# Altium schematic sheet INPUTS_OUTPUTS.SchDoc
size A; SheetNumber: 5; SheetTotal: 5
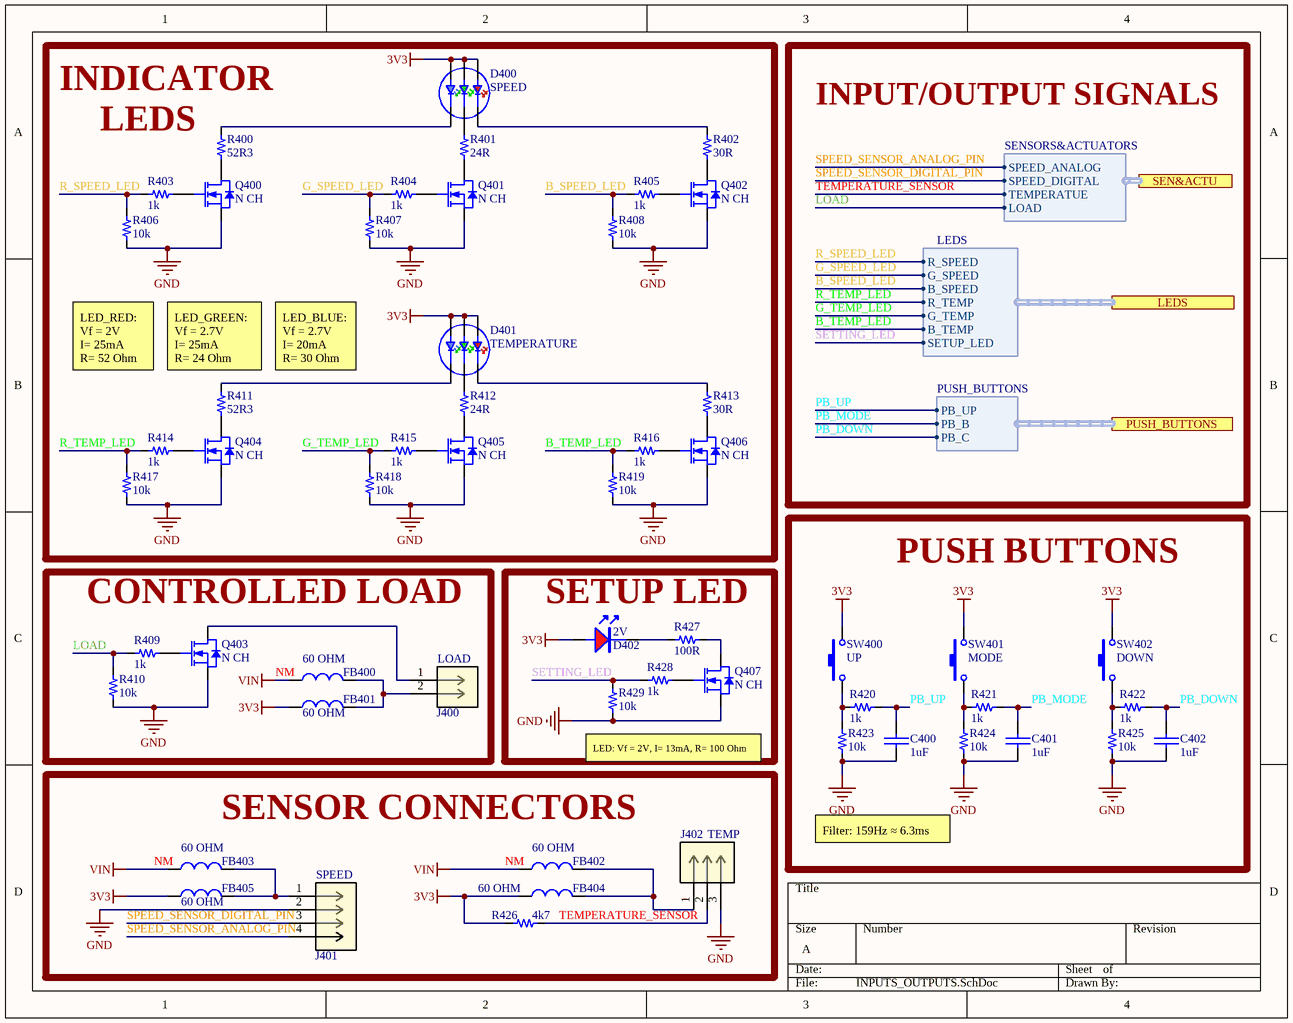
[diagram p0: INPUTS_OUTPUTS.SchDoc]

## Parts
C400  value 1uF  [0603_cap]  (hidden comment: 1uF 50V)
C401  value 1uF  [0603_cap]  (hidden comment: 1uF 50V)
C402  value 1uF  [0603_cap]  (hidden comment: 1uF 50V)
D400  SPEED  [RGB_NS_3.5X3.7]
D401  TEMPERATURE  [RGB_NS_3.5X3.7]
D402  2V  [0805_LED]
FB400  value 60 OHM  Usage: NM  [0603_fb]  (hidden comment: 60OHM 2A)
FB401  value 60 OHM  [0603_fb]  (hidden comment: 60OHM 2A)
FB402  value 60 OHM  Usage: NM  [0603_fb]  (hidden comment: 60OHM 2A)
FB403  value 60 OHM  Usage: NM  [0603_fb]  (hidden comment: 60OHM 2A)
FB404  value 60 OHM  [0603_fb]  (hidden comment: 60OHM 2A)
FB405  value 60 OHM  [0603_fb]  (hidden comment: 60OHM 2A)
J400  LOAD  [CON_2X1_TH_2.54MM]
J401  SPEED  [CON_4X1_TH_2.54MM]
J402  TEMP  [CON_3X1_TH_2.54MM]
Q400  N CH  [SOT_23_3]
Q401  N CH  [SOT_23_3]
Q402  N CH  [SOT_23_3]
Q403  N CH  [SOT_23_3]
Q404  N CH  [SOT_23_3]
Q405  N CH  [SOT_23_3]
Q406  N CH  [SOT_23_3]
Q407  N CH  [SOT_23_3]
R400  value 52R3  [0603_res]  (hidden comment: 52R3 1/10W)
R401  value 24R  [0603_res]  (hidden comment: 24R 1/10W)
R402  value 30R  [0603_res]  (hidden comment: 30 1/10W)
R403  value 1k  [0603_res]  (hidden comment: 1k 1/10W)
R404  value 1k  [0603_res]  (hidden comment: 1k 1/10W)
R405  value 1k  [0603_res]  (hidden comment: 1k 1/10W)
R406  value 10k  [0603_res]  (hidden comment: 10k 1/10W)
R407  value 10k  [0603_res]  (hidden comment: 10k 1/10W)
R408  value 10k  [0603_res]  (hidden comment: 10k 1/10W)
R409  value 1k  [0603_res]  (hidden comment: 1k 1/10W)
R410  value 10k  [0603_res]  (hidden comment: 10k 1/10W)
R411  value 52R3  [0603_res]  (hidden comment: 52R3 1/10W)
R412  value 24R  [0603_res]  (hidden comment: 24R 1/10W)
R413  value 30R  [0603_res]  (hidden comment: 30 1/10W)
R414  value 1k  [0603_res]  (hidden comment: 1k 1/10W)
R415  value 1k  [0603_res]  (hidden comment: 1k 1/10W)
R416  value 1k  [0603_res]  (hidden comment: 1k 1/10W)
R417  value 10k  [0603_res]  (hidden comment: 10k 1/10W)
R418  value 10k  [0603_res]  (hidden comment: 10k 1/10W)
R419  value 10k  [0603_res]  (hidden comment: 10k 1/10W)
R420  value 1k  [0603_res]  (hidden comment: 1k 1/10W)
R421  value 1k  [0603_res]  (hidden comment: 1k 1/10W)
R422  value 1k  [0603_res]  (hidden comment: 1k 1/10W)
R423  value 10k  [0603_res]  (hidden comment: 10k 1/10W)
R424  value 10k  [0603_res]  (hidden comment: 10k 1/10W)
R425  value 10k  [0603_res]  (hidden comment: 10k 1/10W)
R426  value 4k7  [0603_res]  (hidden comment: 4k7 1/10W)
R427  value 100R  [0603_res]  (hidden comment: 100R 1/10W)
R428  value 1k  [0603_res]  (hidden comment: 1k 1/10W)
R429  value 10k  [0603_res]  (hidden comment: 10k 1/10W)
SW400  UP  [Sw_PUSH_4.5x4.5x5mm]
SW401  MODE  [Sw_PUSH_4.5x4.5x5mm]
SW402  DOWN  [Sw_PUSH_4.5x4.5x5mm]

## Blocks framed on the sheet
PUSH BUTTONS: C400-C402 R420-R425 SW400-SW402
CONTROLLED LOAD: FB400 FB401 J400 Q403 R409 R410
SETUP LED: D402 Q407 R427-R429
SENSOR CONNECTORS: FB402-FB405 J401 J402 R426

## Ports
LEDS (harness LEDS, see main[3C], MCU[4C]), PUSH_BUTTONS (harness PUSH_BUTTONS, see main[3C], MCU[4C]), SEN&ACTU (harness SENSORS&ACTUATORS, see main[3C], MCU[4C])

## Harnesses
LEDS: R_SPEED, G_SPEED, B_SPEED, R_TEMP, G_TEMP, B_TEMP, SETUP_LED
SENSORS&ACTUATORS: SPEED_ANALOG, SPEED_DIGITAL, TEMPERATUE, LOAD
PUSH_BUTTONS: PB_UP, PB_B, PB_C

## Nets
3V3: D400.4 D400.5 D400.6 D401.4 D401.5 D401.6 D402.1(A) FB401.1 FB404.1 FB405.1 R426.1 SW400.2 SW401.2 SW402.2
GND: C400.1 C401.1 C402.1 J401.2 J402.3 Q400.2(S) Q401.2(S) Q402.2(S) Q403.2(S) Q404.2(S) Q405.2(S) Q406.2(S) Q407.2(S) R406.1 R407.1 R408.1 R410.1 R417.1 R418.1 R419.1 R423.1 R424.1 R425.1 R429.1
VIN: FB400.1 FB402.1 FB403.1
B_SPEED_LED: R405.1 R408.2 ; port LEDS.B_SPEED
B_TEMP_LED: R416.1 R419.2 ; port LEDS.B_TEMP
G_SPEED_LED: R404.1 R407.2 ; port LEDS.G_SPEED
G_TEMP_LED: R415.1 R418.2 ; port LEDS.G_TEMP
LOAD: R409.1 R410.2 ; port SEN&ACTU.LOAD
PB_DOWN: C402.2 R422.2 ; port PUSH_BUTTONS.PB_C
PB_MODE: C401.2 R421.2 ; port PUSH_BUTTONS.PB_B
PB_UP: C400.2 R420.2 ; port PUSH_BUTTONS.PB_UP
R_SPEED_LED: R403.1 R406.2 ; port LEDS.R_SPEED
R_TEMP_LED: R414.1 R417.2 ; port LEDS.R_TEMP
SETTING_LED: R428.1 R429.2 ; port LEDS.SETUP_LED
SPEED_SENSOR_ANALOG_PIN: J401.4 ; port SEN&ACTU.SPEED_ANALOG
SPEED_SENSOR_DIGITAL_PIN: J401.3 ; port SEN&ACTU.SPEED_DIGITAL
TEMPERATURE_SENSOR: J402.2 R426.2 ; port SEN&ACTU.TEMPERATUE
NetD400_1: D400.1 R400.2
NetD400_2: D400.2 R401.2
NetD400_3: D400.3 R402.2
NetD401_1: D401.1 R411.2
NetD401_2: D401.2 R412.2
NetD401_3: D401.3 R413.2
NetD402_2: D402.2 R427.2
NetFB400_2: FB400.2 FB401.2 J400.2
NetFB402_2: FB402.2 FB404.2 J402.1
NetFB403_2: FB403.2 FB405.2 J401.1
NetJ400_1: J400.1 Q403.3(D)
NetQ400_1: Q400.1(G) R403.2
NetQ400_3: Q400.3(D) R400.1
NetQ401_1: Q401.1(G) R404.2
NetQ401_3: Q401.3(D) R401.1
NetQ402_1: Q402.1(G) R405.2
NetQ402_3: Q402.3(D) R402.1
NetQ403_1: Q403.1(G) R409.2
NetQ404_1: Q404.1(G) R414.2
NetQ404_3: Q404.3(D) R411.1
NetQ405_1: Q405.1(G) R415.2
NetQ405_3: Q405.3(D) R412.1
NetQ406_1: Q406.1(G) R416.2
NetQ406_3: Q406.3(D) R413.1
NetQ407_1: Q407.1(G) R428.2
NetQ407_3: Q407.3(D) R427.1
NetR420_1: R420.1 R423.2 SW400.1
NetR421_1: R421.1 R424.2 SW401.1
NetR422_1: R422.1 R425.2 SW402.1

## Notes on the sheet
- (near R400) INDICATOR
- LEDS
- INPUT/OUTPUT SIGNALS
- LED_RED:
  Vf = 2V
  I= 25mA
  R= 52 Ohm
- (near R411) LED_GREEN:
  Vf = 2.7V
  I= 25mA
  R= 24 Ohm
- LED_BLUE:
  Vf = 2.7V
  I= 20mA
  R= 30 Ohm
- LED: Vf = 2V, I= 13mA, R= 100 Ohm
- Filter: 159Hz ≈ 6.3ms

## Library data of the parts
C400-C402 = Cap_1uF_0603_50V: 50V 1uF X5R ±10% 0603 Multilayer Ceramic Capacitors MLCC - SMD/SMT ROHS; Manufacturer: Samsung Electro-Mechanics; Manufacturer Part Number: CL10A105KB8NNNC
D400 D401 = LED_RGB_3535_SMD: -30℃~+85℃ RGB 110° 3535(mm) Light Emitting Diodes (LED) ROHS; Manufacturer: Foshan NationStar Optoelectronics; Manufacturer Part Number: RS-3535MWAM
D402 = LED_0805_RED: LED RED CLEAR 0805 SMD; Manufacturer: XINGLIGHT; Manufacturer Part Number: XL-2012SURC
FB400-FB405 = FB_60_0603_2A: 2A 1 100mΩ 60Ω@100MHz ±25% 0603 Ferrite Beads ROHS; Manufacturer: TAI-TECH; Manufacturer Part Number: HCB1608KF-600T20
J400 = Con_2x1_TH_2.54mm: CONN HEADER VERT 2POS 2.54MM; Manufacturer: Amphenol ICC (FCI); Manufacturer Part Number: 10129378-902001BLF
J401 = Con_4X1_TH_2.54mm: CONN HEADER VERT 4POS 2.54MM; Manufacturer: Amphenol ICC (FCI); Manufacturer Part Number: 10129378-904001BLF
J402 = Con_3X1_TH_2.54mm: CONN HEADER VERT 3POS 2.54MM; Manufacturer: Amphenol ICC (FCI); Manufacturer Part Number: 10129378-903001BLF
Q400-Q407 = Q_NFET_20V_3.2A_SOT23: MOSFET N-CH 20V SOT23; Manufacturer: Doeshare; Manufacturer Part Number: DN2302S
R400 R411 = Res_52R3_0603_1/10W_1: RES SMD 52R3 OHM 1% 1/10W 0603; Manufacturer: FOJAN; Manufacturer Part Number: FRC0603F52R3TS
R401 R412 = Res_24R_0603_1/10W: RES SMD 24R OHM 5% 1/10W 0603; Manufacturer: FOJAN; Manufacturer Part Number: FRC0603J240 TS
R402 R413 = Res_30R_0603_1/10W: RES SMD 30R OHM 1% 1/10W 0603; Manufacturer: FOJAN; Manufacturer Part Number: FRC0603F30R0TS
R403-R405 R409 R414-R416 R420-R422 R428 = Res_1k_0603_1/10W: RES SMD 1k OHM 5% 1/10W 0603; Manufacturer: FOJAN; Manufacturer Part Number: FRC0603J102 TS
R406-R408 R410 R417-R419 R423-R425 R429 = Res_10k_0603_1/10W: RES SMD 10k OHM 5% 1/10W 0603; Manufacturer: FOJAN; Manufacturer Part Number: FRC0603J103TS
R426 = Res_4k7_0603_1/10W: RES SMD 4k7 OHM 5% 1/10W 0603; Manufacturer: FOJAN; Manufacturer Part Number: FRC0603J472 TS
R427 = Res_100R_0603_1/10W: RES SMD 100R OHM 5% 1/10W 0603; Manufacturer: FOJAN; Manufacturer Part Number: FRC0603J101 TS
SW400-SW402 = Sw_PUSH_4.5x4.5x5.0xmm: SWITCH TACTILE SPST-NO 0.05A 12V; Manufacturer: BZCN; Manufacturer Part Number: TSC015A05026A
